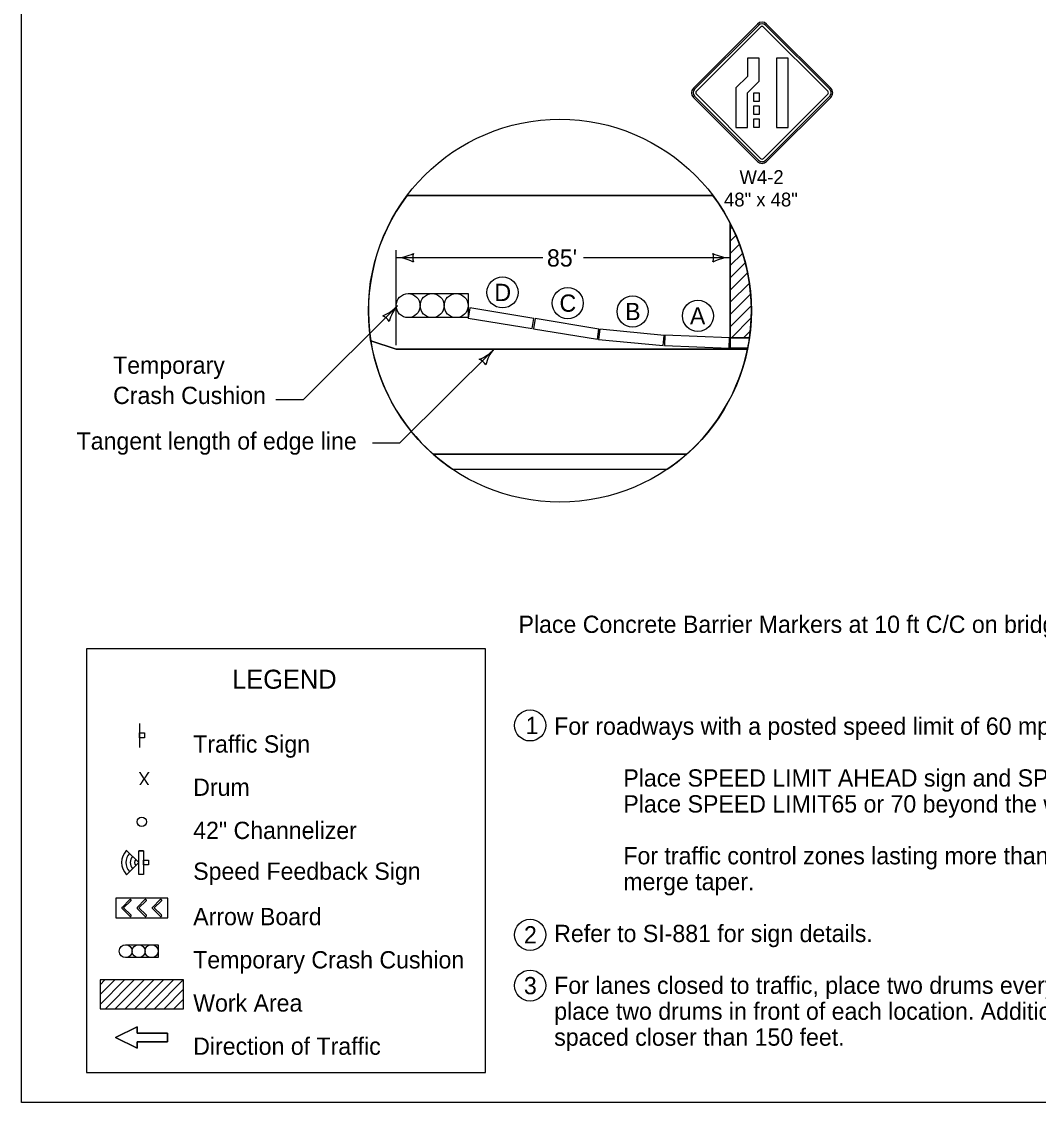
# Model space of a CAD drawing. Extents: x 10133 to 2270741, y 5363 to 1733450.
# Drawn here: x 24533 to 25709, y 7924 to 9175 of the extents above; entities that cross this region are included whole.
import ezdxf

# ---------------------------------------------------------------- set-up
doc = ezdxf.new("R2010")
doc.units = 0
for name, color, linetype in [('dsnNonPlotable', 7, 'Continuous'), ('dsnShtPlotShapeBatchPrint', 7, 'Continuous'), ('dsnStdBlockModified', 7, 'Continuous'), ('dsnStdBorder', 7, 'Continuous'), ('dsnStdLabel', 7, 'Continuous'), ('dsnStdTable', 7, 'Continuous'), ('Level 12', 7, 'Continuous'), ('Level 2', 7, 'Continuous'), ('SheetBorder', 7, 'Continuous')]:
    doc.layers.add(name, color=color, linetype=linetype)

msp = doc.modelspace()

# ---------------------------------------------------------------- linework, layer by layer
at = {"layer": 'dsnNonPlotable'}
for p, q in [((24978.6, 8973.9), (25332.4, 8973.9)), ((25352.6, 8809.1), (25352.6, 8941.6)), ((25352.6, 8935.1), (25354.8, 8937.3)), ((25352.6, 8921), (25359.2, 8927.5)), ((25352.6, 8906.8), (25363.3, 8917.4)), ((25352.6, 8892.7), (25366.9, 8906.9)), ((25352.6, 8878.5), (25370, 8895.9)), ((25352.6, 8864.4), (25372.7, 8884.4)), ((25352.6, 8850.3), (25374.7, 8872.4)), ((25352.6, 8836.1), (25376.2, 8859.7)), ((25352.6, 8822), (25377, 8846.3)), ((25353.9, 8809.1), (25376.9, 8832.1)), ((25368, 8809.1), (25375.8, 8816.8)), ((24936.6, 8805.5), (24965.9, 8796.1)), ((24965.9, 8796.1), (25372.6, 8796.1)), ((25008.9, 8674.3), (25302, 8674.3))]:
    msp.add_line(p, q, dxfattribs=at)
for points in [[(25125.2, 8831.6), (25051.2, 8843.7), (25049.3, 8831.9), (25123.3, 8819.8)], [(25200.7, 8819.2), (25126.7, 8831.4), (25124.8, 8819.5), (25198.8, 8807.4)], [(25276.1, 8812), (25201.5, 8819.1), (25200.3, 8807.2), (25275, 8800.1)], [(25351.9, 8809.1), (25277, 8812.1), (25276.5, 8800.1), (25351.4, 8797.1)]]:
    msp.add_lwpolyline(points, close=True, dxfattribs=at)
for points in [[(25372.8, 8797.1), (25352.6, 8797.1), (25352.6, 8809.1), (25374.8, 8809.1)], [(24607.5, 8448.9), (24607.5, 7958.6), (25069.4, 7958.6), (25069.4, 8448.9), (24607.5, 8448.9)]]:
    msp.add_lwpolyline(points, dxfattribs=at)
at = {"layer": 'dsnShtPlotShapeBatchPrint'}
for centre in [(25089, 8861.7), (25164.5, 8849.3), (25239.6, 8839.6), (25315.2, 8834.6), (25121, 8360.4), (25121, 8118), (25121, 8059.2)]:
    msp.add_circle(centre, 18, dxfattribs=at)
at = {"layer": 'dsnStdBlockModified'}
for p, q in [((24979.8, 8860.3), (25049.3, 8860.3)), ((25049.3, 8860.3), (25049.3, 8832.5)), ((25049.3, 8832.5), (24979.8, 8832.5)), ((25048.7, 8831.2), (25048.7, 8831.2)), ((24653.9, 8215.8), (24668.1, 8201.7)), ((24673.7, 8215.4), (24668.1, 8215.4)), ((24668.1, 8201.7), (24653.9, 8187.5)), ((24673.7, 8187.9), (24668.1, 8187.9))]:
    msp.add_line(p, q, dxfattribs=at)
for centre in [(24979.8, 8846.4), (24979.8, 8846.4), (25007.6, 8846.4), (25007.6, 8846.4), (25035.4, 8846.4), (25035.4, 8846.4)]:
    msp.add_circle(centre, 13.9, dxfattribs=at)
for radius, start, end in [(20.3, 135.88, 224.0313), (15.3, 136.1665, 223.7159), (10.3, 136.7294, 223.0963), (5.32, 138.7005, 221.2995)]:
    msp.add_arc((24668.5, 8201.7), radius, start, end, dxfattribs=at)
at = {"layer": 'dsnStdBorder'}
for p, q in [((25309.9, 9098.1), (25384.1, 9172.4)), ((25384.1, 9172.4), (25309.9, 9098.1)), ((25384.1, 9172.4), (25384.1, 9172.4)), ((25394.7, 9172.4), (25469, 9098.1)), ((25469, 9098.1), (25394.7, 9172.4)), ((25311.2, 9096.8), (25385.5, 9171.1)), ((25387.7, 9168.9), (25313.4, 9094.6)), ((25387.7, 9168.9), (25387.7, 9168.9)), ((25465.5, 9094.6), (25391.2, 9168.9)), ((25393.4, 9171.1), (25467.7, 9096.8)), ((25384.1, 9013.3), (25309.9, 9087.5)), ((25309.9, 9087.5), (25384.1, 9013.3)), ((25385.5, 9014.6), (25311.2, 9088.9)), ((25313.4, 9091.1), (25387.7, 9016.8)), ((25391.2, 9016.8), (25465.5, 9091.1)), ((25467.7, 9088.9), (25393.4, 9014.6)), ((25469, 9087.5), (25394.7, 9013.3)), ((25394.7, 9013.3), (25469, 9087.5)), ((24669, 8362.5), (24669, 8335)), ((24673.7, 8215.4), (24673.7, 8187.9)), ((24648.8, 8149.8), (24657.7, 8158.7)), ((24666.4, 8149.8), (24675.2, 8158.7)), ((24684, 8149.8), (24692.8, 8158.7)), ((24652.9, 8106.6), (24690.4, 8106.6)), ((24690.4, 8106.6), (24690.4, 8091.6)), ((24690.4, 8091.6), (24652.9, 8091.6)), ((24623.3, 8060.1), (24628.9, 8065.7)), ((24623.3, 8048.8), (24640.3, 8065.7)), ((24623.3, 8037.5), (24651.6, 8065.7)), ((24629.6, 8032.5), (24662.9, 8065.7)), ((24640.9, 8032.5), (24674.2, 8065.7)), ((24652.2, 8032.5), (24685.5, 8065.7)), ((24663.5, 8032.5), (24696.8, 8065.7)), ((24674.9, 8032.5), (24708.1, 8065.7)), ((24686.2, 8032.5), (24719.5, 8065.7)), ((24697.5, 8032.5), (24719.9, 8054.9)), ((24708.8, 8032.5), (24719.9, 8043.6))]:
    msp.add_line(p, q, dxfattribs=at)
for points in [[(25385.5, 9171.1), (25311.2, 9096.8)], [(25387.7, 9168.9), (25313.4, 9094.6)], [(25465.5, 9094.6), (25391.2, 9168.9)], [(25467.7, 9096.8), (25393.4, 9171.1)], [(25311.2, 9088.9), (25385.5, 9014.6)], [(25313.4, 9091.1), (25387.7, 9016.8)], [(25391.2, 9016.8), (25465.5, 9091.1)], [(25393.4, 9014.6), (25467.7, 9088.9)], [(24657.7, 8139.5), (24657.6, 8139.6), (24648.8, 8148.4), (24648.8, 8148.4)], [(24659.1, 8157.2), (24659.1, 8157.2), (24650.6, 8149.1), (24659.1, 8141)], [(24675.2, 8139.5), (24675.2, 8139.6), (24666.4, 8148.4), (24666.4, 8148.4)], [(24676.7, 8157.2), (24676.6, 8157.2), (24668.1, 8149.1), (24676.6, 8141)], [(24692.9, 8139.5), (24692.8, 8139.6), (24684, 8148.4), (24684, 8148.4)], [(24694.3, 8157.2), (24694.3, 8157.2), (24685.8, 8149.1), (24694.3, 8141)], [(24666.3, 8004.1), (24666.3, 8011.6), (24641.3, 7999.1), (24666.3, 7986.6), (24666.3, 7994.1), (24701.3, 7994.1), (24701.3, 8004.1), (24666.3, 8004.1)]]:
    msp.add_lwpolyline(points, dxfattribs=at)
for points in [[(25372.4, 9111.7), (25359.2, 9098.4), (25359.2, 9052.8), (25372.7, 9052.8), (25372.7, 9092.8), (25385.9, 9106.1), (25385.9, 9132.8), (25372.4, 9132.8)], [(25406.2, 9132.8), (25406.2, 9052.8), (25419.7, 9052.8), (25419.7, 9132.8)], [(25379.9, 9092.8), (25385.9, 9092.8), (25385.9, 9082.8), (25379.9, 9082.8)], [(25379.9, 9077.8), (25385.9, 9077.8), (25385.9, 9067.8), (25379.9, 9067.8)], [(25379.9, 9062.8), (25385.9, 9062.8), (25385.9, 9052.8), (25379.9, 9052.8)], [(24669.1, 8346.1), (24669.1, 8351.7), (24674.7, 8351.7), (24674.7, 8346.1)], [(24668.1, 8187.9), (24668.1, 8215.4), (24673.7, 8215.4), (24673.7, 8187.9)], [(24673.7, 8199), (24673.7, 8204.6), (24679.3, 8204.6), (24679.3, 8199)], [(24701.6, 8160.6), (24641.6, 8160.6), (24641.6, 8137.6), (24701.6, 8137.6)], [(24623.3, 8065.7), (24623.3, 8032.5), (24719.9, 8032.5), (24719.9, 8065.7)], [(24701.3, 8004.1), (24701.3, 7994.1), (24666.3, 7994.1), (24666.3, 7986.6), (24641.3, 7999.1), (24666.3, 8011.6), (24666.3, 8004.1)]]:
    msp.add_lwpolyline(points, close=True, dxfattribs=at)
for centre, radius in [((25155.5, 8840.5), 221.6), ((24979.8, 8846.4), 13.9), ((25007.6, 8846.4), 13.9), ((25035.4, 8846.4), 13.9), ((24671.6, 8248.9), 5.37), ((24671.6, 8248.9), 5.37), ((24652.9, 8099.1), 7.5), ((24652.9, 8099.1), 7.5), ((24667.9, 8099.1), 7.5), ((24667.9, 8099.1), 7.5), ((24682.9, 8099.1), 7.5), ((24682.9, 8099.1), 7.5)]:
    msp.add_circle(centre, radius, dxfattribs=at)
for centre, radius, start, end in [((25389.4, 9167.1), 7.5, 45.0003, 135), ((25389.4, 9167.1), 7.5, 45.0003, 135), ((25389.4, 9167.1), 5.63, 45.0003, 135), ((25389.4, 9167.1), 5.63, 45.0003, 135), ((25389.4, 9167.1), 2.5, 45.0003, 135), ((25389.4, 9167.1), 2.5, 45.0003, 135), ((25315.2, 9092.8), 7.5, 135.0002, 224.9998), ((25315.2, 9092.8), 7.5, 135.0002, 224.9998), ((25315.2, 9092.8), 5.63, 135.0002, 224.9998), ((25315.2, 9092.8), 5.63, 135.0002, 224.9998), ((25463.7, 9092.8), 5.63, 315, 45.0003), ((25463.7, 9092.8), 5.63, 315, 45.0003), ((25463.7, 9092.8), 7.5, 315, 45.0003), ((25463.7, 9092.8), 7.5, 315, 45.0003), ((25315.2, 9092.8), 2.5, 135.0002, 224.9998), ((25315.2, 9092.8), 2.5, 135.0002, 224.9998), ((25463.7, 9092.8), 2.5, 315, 45.0003), ((25463.7, 9092.8), 2.5, 315, 45.0003), ((25389.4, 9018.6), 7.5, 224.9998, 315), ((25389.4, 9018.6), 7.5, 224.9998, 315), ((25389.4, 9018.6), 5.63, 224.9998, 315), ((25389.4, 9018.6), 5.63, 224.9998, 315), ((25389.4, 9018.6), 2.5, 224.9998, 315), ((25389.4, 9018.6), 2.5, 224.9998, 315), ((24658.4, 8157.9), 1.03, 315.0975, 135.281), ((24675.9, 8157.9), 1.03, 315.0975, 135.281), ((24693.6, 8157.9), 1.03, 315.0975, 135.281), ((24649.6, 8149.1), 1.03, 134.1616, 224.6098), ((24667.1, 8149.1), 1.03, 134.1616, 224.6098), ((24684.7, 8149.1), 1.03, 134.1616, 224.6098), ((24658.4, 8140.3), 1.03, 226.201, 47.3602), ((24675.9, 8140.3), 1.03, 226.201, 47.3602), ((24693.6, 8140.3), 1.03, 226.201, 47.3602)]:
    msp.add_arc(centre, radius, start, end, dxfattribs=at)
at = {"layer": 'dsnStdLabel'}
msp.add_line((25352.6, 8813.6), (25352.6, 8910.6), dxfattribs=at)
at = {"layer": 'Level 12'}
for p, q in [((24965.9, 8800.6), (24965.9, 8910.6)), ((25352.6, 8813.6), (25352.6, 8910.6)), ((25135.9, 8901.9), (24965.9, 8901.9)), ((25352.6, 8901.9), (25182.6, 8901.9)), ((24967.6, 8846.3), (24858.7, 8737.8)), ((25079.3, 8796), (24970.4, 8687.4)), ((24826.7, 8737.8), (24858.7, 8737.8)), ((24938.4, 8687.4), (24970.4, 8687.4))]:
    msp.add_line(p, q, dxfattribs=at)
for centre, radius, start, end in [((24965.9, 8944.4), 42.5, 270, 298.0725), ((24965.9, 8859.4), 42.5, 61.9275, 90), ((25001.6, 8901.9), 16.4, 162.2666, 197.7334), ((25317, 8901.9), 16.4, 342.2666, 17.7334), ((25352.6, 8944.4), 42.5, 241.9275, 270), ((25352.6, 8859.4), 42.5, 90, 118.0725), ((24935.6, 8874.5), 42.5, 290.4723, 318.5448), ((24999.3, 8818.3), 42.5, 138.5448, 166.6173), ((24943.8, 8819.7), 16.4, 30.8115, 66.2782), ((25047.3, 8824.2), 42.5, 290.4723, 318.5448), ((25111, 8768), 42.5, 138.5448, 166.6173), ((25055.6, 8769.4), 16.4, 30.8115, 66.2782)]:
    msp.add_arc(centre, radius, start, end, dxfattribs=at)
at = {"layer": 'Level 2'}
for p, q in [((25332.4, 8973.9), (24978.6, 8973.9)), ((25352.6, 8809.1), (25374.8, 8809.1)), ((24936.6, 8805.5), (24965.9, 8796.1)), ((24965.9, 8796.1), (24936.6, 8805.5)), ((24965.9, 8796.1), (25372.6, 8796.1)), ((25372.6, 8796.1), (24965.9, 8796.1)), ((25008.9, 8674.3), (25302, 8674.3)), ((25302, 8674.3), (25008.9, 8674.3)), ((25031.2, 8657), (25279.7, 8657))]:
    msp.add_line(p, q, dxfattribs=at)
for points in [[(25352.6, 8941.6), (25352.6, 8901.9), (25352.6, 8809.1)], [(25125.2, 8831.6), (25051.2, 8843.7), (25049.3, 8831.9), (25123.3, 8819.8), (25125.2, 8831.6)], [(25200.7, 8819.2), (25126.7, 8831.4), (25124.8, 8819.5), (25198.8, 8807.4), (25200.7, 8819.2)], [(25276.1, 8812), (25201.5, 8819.1), (25200.3, 8807.2), (25275, 8800.1), (25276.1, 8812)], [(25351.9, 8809.1), (25277, 8812.1), (25276.5, 8800.1), (25351.4, 8797.1), (25351.9, 8809.1)], [(25374.8, 8809.1), (25352.6, 8809.1), (25352.6, 8797.1), (25372.8, 8797.1)], [(25372.8, 8797.1), (25352.6, 8797.1), (25352.6, 8809.1), (25374.8, 8809.1)]]:
    msp.add_lwpolyline(points, dxfattribs=at)
for start, end in [(142.9773, 189.0659), (351.8621, 37.0227), (351.8621, 27.1505), (348.7138, 351.8621), (189.0659, 228.5906), (311.4094, 348.45), (348.45, 348.7138), (228.5906, 235.889), (304.111, 311.4094)]:
    msp.add_arc((25155.5, 8840.5), 221.6, start, end, dxfattribs=at)
at = {"layer": 'SheetBorder'}
msp.add_lwpolyline([(24532.5, 9944), (27667.5, 9944), (27667.5, 7924), (24532.5, 7924)], close=True, dxfattribs=at)

# ---------------------------------------------------------------- texts
at = {"layer": 'dsnShtPlotShapeBatchPrint'}
for s, p in [('D', (25079.7, 8851.7)), ('C', (25155, 8839.3)), ('B', (25231, 8829.6)), ('A', (25305.9, 8824.6)), ('1', (25115.8, 8350.4)), ('2', (25113.9, 8108)), ('3', (25113.8, 8049.2))]:
    msp.add_text(s, height=20, dxfattribs=at).set_placement(p)
at = {"layer": 'dsnStdBorder'}
for s, height, p in [('W4-2', 16, (25363.3, 8987.2)), ('48" x 48"', 16, (25345.4, 8961.2)), ('LEGEND', 22, (24776.1, 8402.9)), ('Traffic Sign', 20, (24731.1, 8328.9)), ('Drum', 20, (24731.1, 8278.9)), ('42" Channelizer ', 20, (24731.1, 8228.9)), ('Speed Feedback Sign', 20, (24731.1, 8181.7)), ('Arrow Board', 20, (24731.1, 8129.1)), ('Temporary Crash Cushion', 20, (24731.1, 8079.1)), ('Work Area', 20, (24731.1, 8029.1)), ('Direction of Traffic', 20, (24731.1, 7979.1))]:
    msp.add_text(s, height=height, dxfattribs=at).set_placement(p)
msp.add_text('X', height=15, rotation=180, dxfattribs=at).set_placement((24681.1, 8306.4))
at = {"layer": 'dsnStdTable'}
for s, p in [('Place Concrete Barrier Markers at 10 ft C/C on bridge rail.', (25107.6, 8467.5)), ('For roadways with a posted speed limit of 60 mph or greater before road work:', (25148.9, 8349.6)), ('Place SPEED LIMIT AHEAD sign and SPEED LIMIT 55 sign prior to the lane closure as shown. ', (25228.9, 8289.6)), ('Place SPEED LIMIT65 or 70 beyond the work area as shown.', (25228.9, 8259.6)), ('For traffic control zones lasting more than 4 hours, place a Speed Feedback Sign at the end of the ', (25228.9, 8199.6)), ('merge taper.', (25228.9, 8169.6)), ('Refer to SI-881 for sign details.', (25148.9, 8109.6)), ('For lanes closed to traffic, place two drums every 1000 feet. For full depth excavations in a closed lane, ', (25148.9, 8049.6)), ('place two drums in front of each location. Additional drums need not be placed for full depth excavations ', (25148.9, 8019.6)), ('spaced closer than 150 feet.', (25148.9, 7989.6))]:
    msp.add_text(s, height=20, dxfattribs=at).set_placement(p)
at = {"layer": 'Level 12'}
for s, p in [("85'", (25140.5, 8891.6)), ('Temporary ', (24638.4, 8767.5)), ('Crash Cushion', (24638.4, 8732.5)), ('Tangent length of edge line', (24596.2, 8679.7))]:
    msp.add_text(s, height=20, dxfattribs=at).set_placement(p)

doc.saveas('drawing.dxf')
